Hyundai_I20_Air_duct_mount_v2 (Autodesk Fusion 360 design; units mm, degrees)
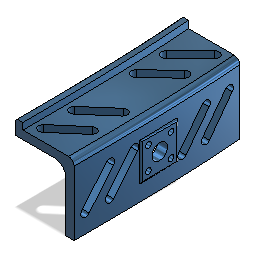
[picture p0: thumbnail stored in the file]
sketch "Sketch1"
  line L1 (1.8812, 40.2376) -> (4.8812, 40.2376)
  line L2 (0.8812, 39.2376) -> (1.8812, 40.2376)
  line L3 (0.8812, 32.3376) -> (0.8812, 39.2376)
  line L4 (21.4812, 32.3376) -> (0.8812, 32.3376)
  line L5 (27.4812, -0.2624) -> (27.4812, 26.3376)
  line L6 (31.8812, -0.2624) -> (27.4812, -0.2624)
  line L7 (31.8812, 33.7376) -> (31.8812, -0.2624)
  line L8 (4.8812, 36.7376) -> (28.8812, 36.7376)
  line L9 (4.8812, 40.2376) -> (4.8812, 36.7376)
  arc A1 centre (21.4812, 26.3376) radius 6 clockwise from (21.4812, 32.3376) to (27.4812, 26.3376)
  arc A2 centre (28.8812, 33.7376) radius 3 clockwise from (28.8812, 36.7376) to (31.8812, 33.7376)
  point P7 (27.4812, -0.2624)
  point P8 (31.8812, -0.2624)
  point P6 (4.8812, 40.2376)
  point P9 (1.8812, 40.2376)
  dimension "d47" distance P7 P8 = 4.4
  dimension "d60" radius A1 = 6
  dimension "d92" radius A2 = 3
  dimension "d109" distance L4 L8 = 4.4 (= "d47")
  dimension "d111" distance L6 L8 = 37
  dimension "d112" distance L3 L7 = 31
  dimension "d113" distance P6 P9 = 3
  dimension "d114" distance L3 L9 = 4
  dimension "d115" distance L1 L8 = 3.5
sketch "Sketch2" plane through (0, 0, 0) normal (0, 1, 0) x axis (1, 0, 0)
  line L1 (10, 90) -> (10, 0)
  line L2 (-10, 90) -> (10, 90)
  curve K1 (-2.85, 90) -> (0, 0)
  curve K2 (-3.6434, 99) -> (-2.0566, 81)
  point P2 (10, 0)
  point P3 (10, 90)
  point P1 (0, 0)
  point P4 (-10, 90)
  point P6 (-2.85, 90)
  dimension "d1" distance P2 P3 = 90
  dimension "d88" distance P1 P2 = 10
  dimension "d89" distance P3 P4 = 20
  dimension "d90" distance P3 P6 = 12.85
  dimension "d91" distance P1 P4 = 10
sweep "Sweep1" sketch "Sketch1" TwistAngle 0 TaperAngle 0
sketch "Sketch4" plane through (0, 0, 0) normal (0, 1, 0) x axis (1, 0, 0)
  line L1 (6.4158, 74.0671) -> (19.1437, 86.795)
  line L2 (22.6792, 83.2595) -> (9.9513, 70.5315)
  line L3 (8.1836, 72.2993) -> (20.9115, 85.0272)
  arc A1 centre (8.1836, 72.2993) radius 2.5 clockwise from (9.9513, 70.5315) to (6.4158, 74.0671)
  arc A2 centre (20.9115, 85.0272) radius 2.5 clockwise from (19.1437, 86.795) to (22.6792, 83.2595)
  point P1 (0, 0)
  point P6 (20.9115, 85.0272)
  dimension "d8" diameter A1 = 5
  dimension "d98" distance P1 P6 = 20.9115
  dimension "d11" R-Pattern1-uDistance = 0
  dimension "d12" R-Pattern1-vDistance = -65
extrude "Extrude1" cut sketch "Sketch4" profile of L1 A1 L2 A2 along normal blind 55
path_pattern "PathPattern2" PathPatternDelta 65.425
work_plane "WorkPlane1" AlongDistance 43
sketch "Sketch9" plane through (0, 0, 0) normal (1, 0, 0) x axis (0, 0, -1)
  line L1 (20.7709, 23.7139) -> (7.9151, 8.393)
  line L2 (4.0849, 11.607) -> (16.9406, 26.9279)
  line L3 (18.8558, 25.3209) -> (6, 10)
  line L4 (92.7605, -0.2624) -> (0, -0.2624)
  line L5 (17.0849, 11.607) -> (29.9406, 26.9279)
  line L6 (33.7709, 23.7139) -> (20.9151, 8.393)
  line L7 (56.0849, 11.607) -> (68.9406, 26.9279)
  line L8 (72.7709, 23.7139) -> (59.9151, 8.393)
  line L9 (69.0849, 11.607) -> (81.9406, 26.9279)
  line L10 (85.7709, 23.7139) -> (72.9151, 8.393)
  arc A1 centre (18.8558, 25.3209) radius 2.5 clockwise from (16.9406, 26.9279) to (20.7709, 23.7139)
  arc A2 centre (6, 10) radius 2.5 clockwise from (7.9151, 8.393) to (4.0849, 11.607)
  arc A3 centre (19, 10) radius 2.5 clockwise from (20.9151, 8.393) to (17.0849, 11.607)
  arc A4 centre (31.8558, 25.3209) radius 2.5 clockwise from (29.9406, 26.9279) to (33.7709, 23.7139)
  arc A5 centre (58, 10) radius 2.5 clockwise from (59.9151, 8.393) to (56.0849, 11.607)
  arc A6 centre (70.8558, 25.3209) radius 2.5 clockwise from (68.9406, 26.9279) to (72.7709, 23.7139)
  arc A7 centre (71, 10) radius 2.5 clockwise from (72.9151, 8.393) to (69.0849, 11.607)
  arc A8 centre (83.8558, 25.3209) radius 2.5 clockwise from (81.9406, 26.9279) to (85.7709, 23.7139)
  point P1 (0, 0)
  point P6 (6, 10)
  point P7 (18.8558, 25.3209)
  dimension "d33" diameter A1 = 5
  dimension "d34" distance P1 P6 = 10
  dimension "d35" distance P1 P6 = 6
  dimension "d36" distance P6 P7 = 20
  dimension "d37" angle L3 L4 = 50
  dimension "d42" = 83
  dimension "d40" R-Pattern1-uDistance = 65
  dimension "d41" R-Pattern1-vDistance = 0
extrude "Extrude4" cut sketch "Sketch9" profile of L1 A1 L2 A2 L5 A3 A4 L6 L7 A5 A6 L8 L9 A7 A8 L10 no distance stored
sketch "Sketch10" plane through (43, 0, 0) normal (1, 0, 0) x axis (0, 0, -1)
  line L1 (55, 28) -> (35, 28)
  line L2 (55, 8) -> (55, 28)
  line L3 (35, 8) -> (55, 8)
  line L4 (35, 28) -> (35, 8)
  point P2 (35, 28)
  point P3 (55, 28)
  point P4 (55, 8)
  point P1 (0, 0)
  dimension "d62" distance P2 P3 = 20
  dimension "d63" distance P3 P4 = 20
  dimension "d64" distance P1 L4 = 35
  dimension "d65" distance P1 L3 = 8
extrude "Extrude5" add sketch "Sketch10" against normal blind 14 and against normal blind 11
sketch "Sketch11" plane through (32, 0, 0) normal (1, 0, 0) x axis (0, 0, -1)
  line L1 (55, 8) -> (35, 8)
  line L2 (55, 28) -> (55, 8)
  line L3 (35, 28) -> (55, 28)
  line L4 (35, 8) -> (35, 28)
  circle C1 centre (39, 12) radius 1.5
  circle C2 centre (51, 12) radius 1.5
  circle C3 centre (39, 24) radius 1.5
  circle C4 centre (51, 24) radius 1.5
  circle C5 centre (45, 18) radius 4.1
  point P6 (39, 12)
  point P2 (35, 8)
  point P10 (45, 18)
  dimension "d70" diameter C1 = 3
  dimension "d71" distance L1 P6 = 4
  dimension "d72" distance L4 P6 = 4 (= "d71")
  dimension "d78" diameter C5 = 8.2
  dimension "d79" distance P2 P10 = 10
  dimension "d80" distance P2 P10 = 10 (= "d79")
  dimension "d75" R-Pattern1-uDistance = 12
  dimension "d76" R-Pattern1-vDistance = 12
extrude "Extrude6" cut sketch "Sketch11" profile of C1 C2 C3 C4 C5 no distance stored
fillet "Fillet8" radius 1
work_plane "WorkPlane4" AlongDistance -5.552
sketch "Sketch12" plane through (26.448, 0, 0) normal (1, 0, 0) x axis (0, 0, 1)
  line L1 (-35, 8) -> (-55, 8)
  line L2 (-35, 28) -> (-35, 8)
  line L3 (-55, 8) -> (-55, 26.8001)
  circle C1 centre (-51, 12) radius 1.5
  circle C2 centre (-39, 12) radius 1.5
  circle C3 centre (-51, 24) radius 1.5
  circle C4 centre (-39, 24) radius 1.5
  circle C5 centre (-45, 18) radius 4.1
  circle C6 centre (-51, 24) radius 4
  circle C7 centre (-39, 24) radius 4
  circle C8 centre (-39, 12) radius 4
  circle C9 centre (-51, 12) radius 4
  circle C10 centre (-51, -12) radius 3
  circle C11 centre (-39, -12) radius 3
  circle C12 centre (-51, -24) radius 3
  circle C13 centre (-39, -24) radius 3
  dimension "d82" diameter C6 = 8
  dimension "d83" diameter C9 = 8 (= "d82")
  dimension "d84" diameter C7 = 8 (= "d82")
  dimension "d85" diameter C8 = 8 (= "d82")
  dimension "d105" diameter C11 = 6
  dimension "d106" diameter C12 = 6 (= "d105")
  dimension "d107" diameter C13 = 6 (= "d105")
  dimension "d108" diameter C10 = 6 (= "d105")
extrude "Extrude7" cut sketch "Sketch12" profile of C1 C2 C3 C4 C6 C7 C8 C9 C10 C11 C12 C13 distance -2
work_plane "WorkPlane3" AlongDistance -90
split "Split2"
remove_body "RemoveBody1"
draft "Draft1" Angle1 0.2 Angle2 0
offset_faces "OffsetFaces4" distance 5
offset_faces "OffsetFaces5" distance 5
work_plane "WorkPlane2" AlongDistance 10
split "Split1"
